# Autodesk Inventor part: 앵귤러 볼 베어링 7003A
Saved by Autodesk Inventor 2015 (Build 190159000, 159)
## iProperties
Created: 2024-12
Part Number: 앵귤러 볼 베어링 7003A
Material: 일반
Document SubType Name: Modeling
Designer: 102-5
Density: 1 g/cm^3
Appearance: 기본값
Author: 102-5
Author: jhkim
Description: 앵귤러 콘택트 볼 베어링
Creation Date: 2024-11-28
Sending System: Autodesk Inventor 2025
Preprocessor: ST-DEVELOPER v20
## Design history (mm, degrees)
node "앵귤러 볼 베어링 7003A1"
body "Solid1"
node "Solid1_1"
node "Solid1_2"
node "Solid1_3"
node "Solid1_4"
node "Solid1_5"
node "Solid1_6"
node "Solid1_7"
node "Solid1_8"
node "Solid1_9"
node "Solid1_10"
node "기준1"
node "기준2"
node "기준3"
node "기준4"
node "기준5"
node "기준6"
node "기준7"
node "기준8"
node "기준9"
node "기준10"
node "기준11"
